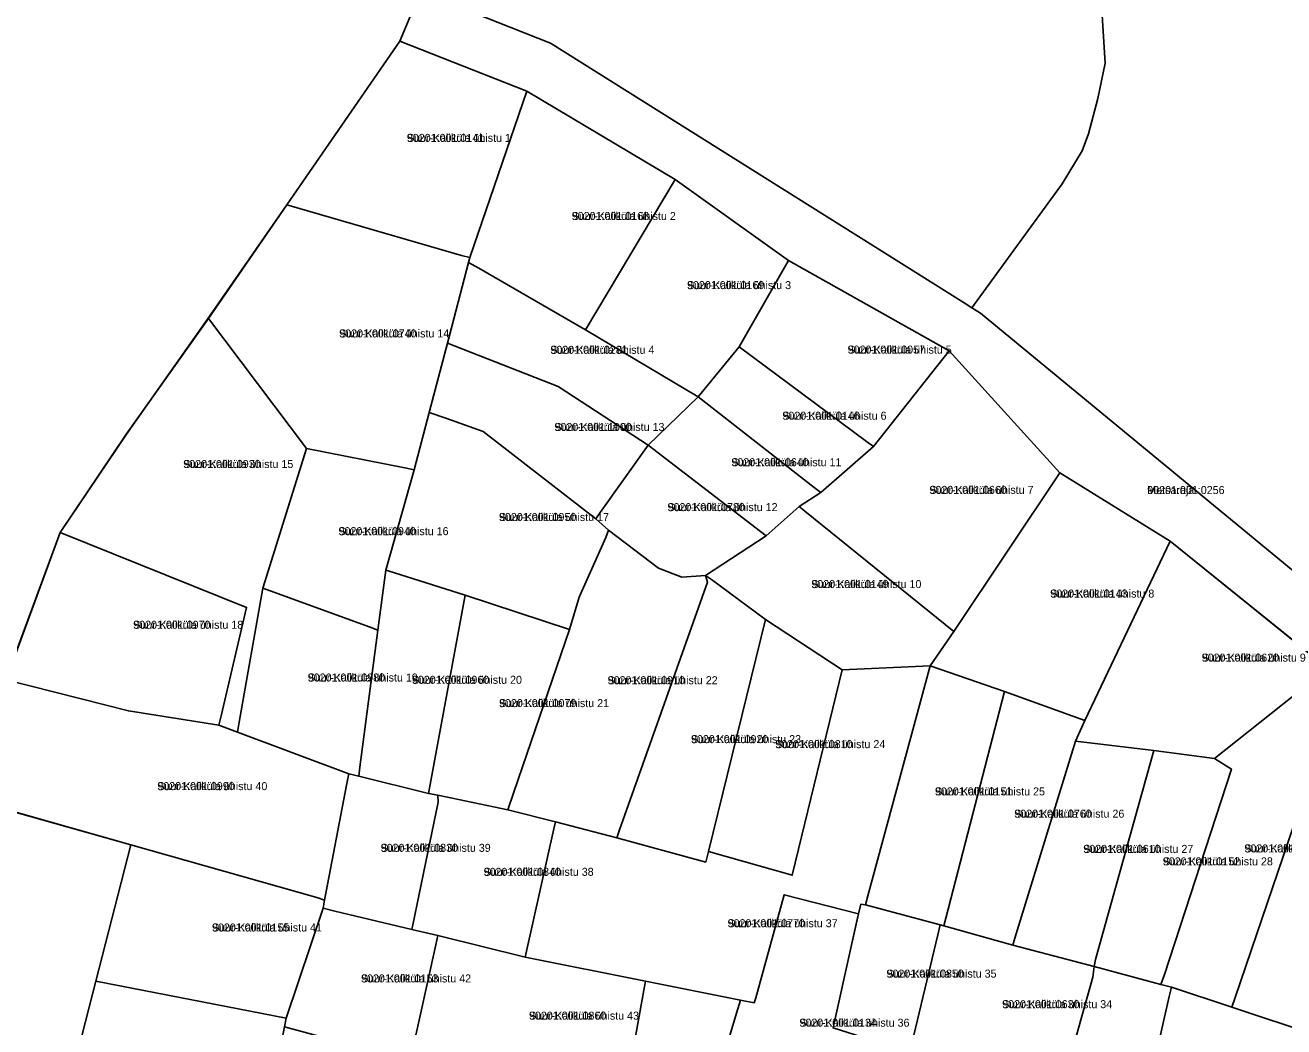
# Model space of a CAD drawing. Extents: x 634518 to 667988, y 6584667 to 6604739.
# Drawn here: x 639044.6 to 639280.5, y 6598932.5 to 6599120.4 of the extents above; entities that cross this region are included whole.
import ezdxf

# ---------------------------------------------------------------- set-up
doc = ezdxf.new("R2010")
doc.units = 0
for name, color, linetype in [('L_AADRESS', 7, 'Continuous'), ('PIIR', 7, 'Continuous'), ('TUNNUS', 7, 'Continuous')]:
    doc.layers.add(name, color=color, linetype=linetype)

msp = doc.modelspace()

# ---------------------------------------------------------------- linework, layer by layer
at = {"layer": 'PIIR'}
for points in [[(638939.52, 6598922.84), (638956.22, 6599045.86), (638963.81, 6599131.43), (639036.47, 6599305.14), (639066.16, 6599272.46), (639113.06, 6599217.03), (639136.09, 6599200.35), (639153.39, 6599188.58), (639173.59, 6599187.14), (639118.65, 6599126.67), (639114.82, 6599117.34), (639093.64, 6599086.65), (639078.76, 6599065.25), (639063.55, 6599043.7), (639051.11, 6599025.24), (639040.95, 6598997.58), (639033.5, 6598975.34), (639064.36, 6598966.67), (639057.8, 6598941.11), (639047.63, 6598901.35)], [(639143.03, 6599116.99), (639118.65, 6599126.67), (639173.59, 6599187.14), (639209.09, 6599197.48), (639243.23, 6599188.58), (639245.19, 6599188.04), (639243.83, 6599180.32), (639244.87, 6599174.9), (639249.45, 6599160.16), (639248.51, 6599133.96), (639246.5, 6599122.2), (639247.04, 6599113.24), (639245.63, 6599106.61), (639243.91, 6599100), (639242.74, 6599096.83), (639238.97, 6599090.63), (639222.06, 6599067.35), (639220.59, 6599068.27)], [(639295.43, 6599007.23), (639223.67, 6599066.34), (639222.06, 6599067.35), (639238.97, 6599090.63), (639242.74, 6599096.83), (639243.91, 6599100), (639245.63, 6599106.61), (639247.04, 6599113.24), (639246.5, 6599122.2), (639248.51, 6599133.96), (639249.45, 6599160.16), (639244.87, 6599174.9), (639243.83, 6599180.32), (639245.19, 6599188.04), (639246.74, 6599187.59), (639297.96, 6599174.25), (639333.44, 6599165.02), (639341.87, 6599103.62), (639355.62, 6599071.96)], [(639166.41, 6599091.4), (639138.6, 6599108), (639114.82, 6599117.34), (639118.65, 6599126.67), (639143.03, 6599116.99), (639220.59, 6599068.27), (639222.06, 6599067.35), (639223.67, 6599066.34), (639295.43, 6599007.23), (639321.52, 6598983.41), (639346.67, 6598960.5), (639375.78, 6598947.36), (639371.97, 6598938.2), (639341.23, 6598951.98), (639313.88, 6598975.86), (639288.82, 6598999.72), (639259.24, 6599023.6), (639238.53, 6599036.45), (639217.78, 6599059.27), (639187.67, 6599076.21)], [(639114.82, 6599117.34), (639138.6, 6599108), (639127.92, 6599076.79), (639126.34, 6599077.18), (639093.64, 6599086.65)], [(639138.6, 6599108), (639166.41, 6599091.4), (639149.6, 6599063.22), (639129.64, 6599074.77), (639127.66, 6599075.84), (639127.92, 6599076.79)], [(639166.41, 6599091.4), (639187.67, 6599076.21), (639178.44, 6599060.02), (639170.71, 6599050.7), (639149.6, 6599063.22)], [(639093.64, 6599086.65), (639126.34, 6599077.18), (639127.92, 6599076.79), (639127.66, 6599075.84), (639123.75, 6599060.75), (639120.32, 6599047.73), (639117.49, 6599036.98), (639115.76, 6599037.37), (639097.31, 6599041.01), (639078.95, 6599065.39)], [(639187.67, 6599076.21), (639217.78, 6599059.27), (639203.59, 6599041.35), (639202.29, 6599042.31), (639178.44, 6599060.02)], [(639127.66, 6599075.84), (639129.64, 6599074.77), (639149.6, 6599063.22), (639170.71, 6599050.7), (639161.38, 6599041.63), (639144.5, 6599052.61), (639125.16, 6599060.19), (639123.75, 6599060.75)], [(639063.59, 6599043.71), (639078.95, 6599065.39), (639097.31, 6599041.01), (639089.13, 6599014.79), (639084.7, 6598989.68), (639084.37, 6598987.8), (639080.9, 6598989.12), (639081.32, 6598990.84), (639086.07, 6599011.17), (639051.1, 6599025.24)], [(639125.16, 6599060.19), (639144.5, 6599052.61), (639161.38, 6599041.63), (639152.37, 6599028.97), (639151.53, 6599027.78), (639130.44, 6599044.2), (639123.43, 6599046.65), (639120.32, 6599047.73), (639123.75, 6599060.75)], [(639178.44, 6599060.02), (639202.29, 6599042.31), (639203.59, 6599041.35), (639193.71, 6599032.74), (639192.49, 6599033.69), (639170.71, 6599050.7)], [(639189.65, 6599030.12), (639193.71, 6599032.74), (639203.59, 6599041.35), (639217.78, 6599059.27), (639238.53, 6599036.45), (639218.66, 6599006.64), (639190.72, 6599029.21)], [(639170.71, 6599050.7), (639192.49, 6599033.69), (639193.71, 6599032.74), (639189.65, 6599030.12), (639183.51, 6599024.63), (639182.41, 6599025.39), (639161.38, 6599041.63)], [(639113.63, 6599017.73), (639112.19, 6599018.15), (639117.49, 6599036.98), (639120.32, 6599047.73), (639123.43, 6599046.65), (639130.44, 6599044.2), (639151.53, 6599027.78), (639153.95, 6599025.65), (639153.43, 6599024.27), (639148.4, 6599013.09), (639146.62, 6599007.02), (639127.04, 6599013.51)], [(639097.31, 6599041.01), (639115.76, 6599037.37), (639117.49, 6599036.98), (639112.19, 6599018.15), (639110.71, 6599006.94), (639109.27, 6599007.46), (639089.13, 6599014.79)], [(639153.95, 6599025.65), (639151.53, 6599027.78), (639152.37, 6599028.97), (639161.38, 6599041.63), (639182.41, 6599025.39), (639183.51, 6599024.63), (639172.13, 6599017.19), (639167.66, 6599016.86), (639163.3, 6599018.57)], [(639238.53, 6599036.45), (639259.24, 6599023.6), (639243.2, 6598989.99), (639228.14, 6598995.39), (639214.22, 6599000.25), (639218.66, 6599006.64)], [(639189.65, 6599030.12), (639190.72, 6599029.21), (639218.66, 6599006.64), (639214.22, 6599000.25), (639197.72, 6598999.5), (639183.33, 6599008.93), (639173.22, 6599016.39), (639172.13, 6599017.19), (639183.51, 6599024.63)], [(639040.98, 6598997.58), (639051.1, 6599025.24), (639086.07, 6599011.17), (639081.32, 6598990.84), (639080.9, 6598989.12), (639063.91, 6598991.76)], [(639135.06, 6598973.24), (639136.18, 6598976.53), (639146.62, 6599007.02), (639148.4, 6599013.09), (639153.43, 6599024.27), (639153.95, 6599025.65), (639163.3, 6599018.57), (639167.66, 6599016.86), (639172.13, 6599017.19), (639172.46, 6599015.92), (639156, 6598969.49), (639155.46, 6598967.96), (639143.98, 6598970.96)], [(639241.46, 6598986.1), (639243.2, 6598989.99), (639259.24, 6599023.6), (639288.8, 6598999.71), (639267.55, 6598982.88), (639256.15, 6598984.38)], [(639107.33, 6598981.23), (639110.71, 6599006.94), (639112.19, 6599018.15), (639113.63, 6599017.73), (639127.04, 6599013.51), (639120.61, 6598978.66), (639120.18, 6598976.31), (639107.11, 6598979.51)], [(639156, 6598969.49), (639172.46, 6599015.92), (639172.13, 6599017.19), (639173.22, 6599016.39), (639183.33, 6599008.93), (639172.64, 6598965.39), (639172.16, 6598963.43), (639155.46, 6598967.96)], [(639084.7, 6598989.68), (639089.13, 6599014.79), (639109.27, 6599007.46), (639110.71, 6599006.94), (639107.33, 6598981.23), (639107.11, 6598979.51), (639105.23, 6598979.95), (639084.37, 6598987.8)], [(639127.04, 6599013.51), (639146.62, 6599007.02), (639136.18, 6598976.53), (639135.06, 6598973.24), (639121.92, 6598975.95), (639120.18, 6598976.31), (639120.61, 6598978.66)], [(639183.33, 6599008.93), (639197.72, 6598999.5), (639188.38, 6598960.95), (639172.64, 6598965.39)], [(639214.22, 6599000.25), (639202.54, 6598957.07), (639202.11, 6598955.44), (639201.23, 6598955.56), (639200.79, 6598953.74), (639186.87, 6598957.3), (639181.54, 6598937.98), (639181.22, 6598937.04), (639178.65, 6598937.56), (639160.85, 6598941.12), (639138.28, 6598945.61), (639138.52, 6598946.71), (639143.68, 6598969.64), (639143.98, 6598970.96), (639155.46, 6598967.96), (639172.16, 6598963.43), (639172.64, 6598965.39), (639188.38, 6598960.95), (639197.72, 6598999.5)], [(639214.22, 6599000.25), (639228.14, 6598995.39), (639217.17, 6598952.94), (639216.79, 6598951.47), (639216.08, 6598951.66), (639202.11, 6598955.44), (639202.54, 6598957.07)], [(639270.78, 6598936.2), (639259.44, 6598939.94), (639257.47, 6598940.45), (639258.17, 6598942.36), (639270.69, 6598980.86), (639267.55, 6598982.88), (639288.8, 6598999.71), (639284.4, 6598976.23), (639271.38, 6598938.02)], [(639270.78, 6598936.2), (639271.38, 6598938.02), (639284.4, 6598976.23), (639288.8, 6598999.71), (639313.89, 6598975.84), (639296.8, 6598926.09), (639286.75, 6598930.92)], [(639040.98, 6598997.58), (639063.91, 6598991.76), (639080.9, 6598989.12), (639084.37, 6598987.8), (639105.23, 6598979.95), (639104.9, 6598978.18), (639100.71, 6598956.26), (639099.22, 6598956.8), (639064.36, 6598966.67), (639033.51, 6598975.39)], [(639216.79, 6598951.47), (639217.17, 6598952.94), (639228.14, 6598995.39), (639243.2, 6598989.99), (639241.46, 6598986.1), (639230.12, 6598949.17), (639229.71, 6598947.85)], [(639256.15, 6598984.38), (639245.2, 6598945.17), (639244.99, 6598943.84), (639229.71, 6598947.85), (639230.12, 6598949.17), (639241.46, 6598986.1)], [(639256.15, 6598984.38), (639267.55, 6598982.88), (639270.69, 6598980.86), (639258.17, 6598942.36), (639257.47, 6598940.45), (639244.99, 6598943.84), (639245.2, 6598945.17)], [(639100.43, 6598954.77), (639100.71, 6598956.26), (639104.9, 6598978.18), (639105.23, 6598979.95), (639107.11, 6598979.51), (639120.18, 6598976.31), (639121.92, 6598975.95), (639122, 6598974.66), (639117.25, 6598951.68), (639117.04, 6598950.79), (639102.61, 6598954.25)], [(639117.04, 6598950.79), (639117.25, 6598951.68), (639122, 6598974.66), (639121.92, 6598975.95), (639135.06, 6598973.24), (639143.98, 6598970.96), (639143.68, 6598969.64), (639138.52, 6598946.71), (639138.28, 6598945.61), (639121.91, 6598949.63)], [(639064.36, 6598966.67), (639099.22, 6598956.8), (639100.71, 6598956.26), (639100.43, 6598954.77), (639093.52, 6598934.15), (639057.8, 6598941.11)], [(639186.87, 6598957.3), (639200.79, 6598953.74), (639200.67, 6598953.2), (639199.3, 6598947.05), (639196.2, 6598933.19), (639196.01, 6598932.34), (639207.23, 6598928.76), (639206.63, 6598926.69), (639200.95, 6598906.88), (639200.52, 6598905.37), (639172.35, 6598913.64), (639172.21, 6598916.11), (639177.91, 6598935.09), (639178.65, 6598937.56), (639181.22, 6598937.04), (639181.54, 6598937.98)], [(639100.43, 6598954.77), (639102.61, 6598954.25), (639117.04, 6598950.79), (639121.91, 6598949.63), (639121.56, 6598947.93), (639117.01, 6598927.26), (639116.7, 6598926.17), (639093.18, 6598932.53), (639093.52, 6598934.15)], [(639196.2, 6598933.19), (639199.3, 6598947.05), (639200.79, 6598953.74), (639201.23, 6598955.56), (639202.11, 6598955.44), (639216.08, 6598951.66), (639215.67, 6598949.8), (639210.76, 6598929.39), (639210.33, 6598927.78), (639207.23, 6598928.76), (639196.01, 6598932.34)], [(639210.33, 6598927.78), (639210.76, 6598929.39), (639215.67, 6598949.8), (639216.08, 6598951.66), (639216.79, 6598951.47), (639229.71, 6598947.85), (639244.99, 6598943.84), (639244.7, 6598941.84), (639239.04, 6598921.58), (639238.71, 6598920.4), (639221.4, 6598924.82)], [(639117.01, 6598927.26), (639121.56, 6598947.93), (639121.91, 6598949.63), (639138.28, 6598945.61), (639160.85, 6598941.12), (639160.67, 6598940.12), (639156.96, 6598919.57), (639156.68, 6598918.13), (639146.93, 6598920.16), (639127.44, 6598924.03), (639116.7, 6598926.17)], [(639239.04, 6598921.58), (639244.7, 6598941.84), (639244.99, 6598943.84), (639257.47, 6598940.45), (639259.44, 6598939.94), (639259.01, 6598938.25), (639254.49, 6598918.07), (639254.25, 6598916.93), (639250.61, 6598917.53), (639238.71, 6598920.4)], [(638939.52, 6598922.84), (639047.63, 6598901.35), (639057.8, 6598941.11), (639093.52, 6598934.15), (639093.18, 6598932.53), (639085.55, 6598894.14), (639061.6, 6598898.73), (639053.29, 6598849.93), (638932.7, 6598820.51)], [(639160.85, 6598941.12), (639178.65, 6598937.56), (639177.91, 6598935.09), (639172.21, 6598916.11), (639172.35, 6598913.64), (639172.49, 6598911.07), (639165.79, 6598879.46), (639165.59, 6598878.52), (639161.31, 6598879.37), (639151.84, 6598881.28), (639141.76, 6598883.34), (639140.02, 6598883.69), (639140.27, 6598885), (639146.63, 6598918.6), (639146.93, 6598920.16), (639156.68, 6598918.13), (639156.96, 6598919.57), (639160.67, 6598940.12)], [(639259.01, 6598938.25), (639259.44, 6598939.94), (639270.78, 6598936.2), (639286.75, 6598930.92), (639285.94, 6598928.24), (639279.92, 6598910.88), (639254.25, 6598916.93), (639254.49, 6598918.07)]]:
    msp.add_lwpolyline(points, close=True, dxfattribs=at)

# ---------------------------------------------------------------- texts
at = {"layer": 'L_AADRESS'}
for s, p in [('Suur-Kaliküla ühistu 1', (639116.12, 6599098.48)), ('Suur-Kaliküla ühistu 2', (639147.03, 6599083.83)), ('Suur-Kaliküla ühistu 3', (639168.64, 6599070.87)), ('Suur-Kaliküla ühistu 14', (639103.44, 6599061.81)), ('Suur-Kaliküla ühistu 4', (639143.02, 6599058.74)), ('Suur-Kaliküla ühistu 5', (639198.75, 6599058.78)), ('Suur-Kaliküla ühistu 6', (639186.53, 6599046.38)), ('Suur-Kaliküla ühistu 13', (639143.79, 6599044.27)), ('Suur-Kaliküla ühistu 15', (639074.21, 6599037.32)), ('Suur-Kaliküla ühistu 11', (639176.96, 6599037.66)), ('Suur-Kaliküla ühistu 7', (639214.09, 6599032.47)), ('Metsaraja', (639254.92, 6599032.44)), ('Suur-Kaliküla ühistu 17', (639133.39, 6599027.38)), ('Suur-Kaliküla ühistu 12', (639164.99, 6599029.24)), ('Suur-Kaliküla ühistu 16', (639103.31, 6599024.73)), ('Suur-Kaliküla ühistu 10', (639191.95, 6599014.81)), ('Suur-Kaliküla ühistu 8', (639236.73, 6599013.03)), ('Suur-Kaliküla ühistu 18', (639064.82, 6599007.18)), ('Suur-Kaliküla ühistu 9', (639265.13, 6599001.02)), ('Suur-Kaliküla ühistu 19', (639097.54, 6598997.29)), ('Suur-Kaliküla ühistu 20', (639117.07, 6598996.86)), ('Suur-Kaliküla ühistu 22', (639153.76, 6598996.78)), ('Suur-Kaliküla ühistu 21', (639133.4, 6598992.49)), ('Suur-Kaliküla ühistu 23', (639169.39, 6598985.73)), ('Suur-Kaliküla ühistu 24', (639185.18, 6598984.79)), ('Suur-Kaliküla ühistu 40', (639069.34, 6598976.92)), ('Suur-Kaliküla ühistu 25', (639215.12, 6598975.93)), ('Suur-Kaliküla ühistu 26', (639230, 6598971.75)), ('Suur-Kaliküla ühistu 39', (639111.21, 6598965.35)), ('Suur-Kaliküla ühistu 27', (639242.93, 6598965.15)), ('Suur-Kaliküla ühistu 29', (639273.13, 6598965.24)), ('Suur-Kaliküla ühistu 28', (639257.84, 6598962.81)), ('Suur-Kaliküla ühistu 38', (639130.51, 6598960.85)), ('Suur-Kaliküla ühistu 41', (639079.58, 6598950.41)), ('Suur-Kaliküla ühistu 37', (639176.25, 6598951.21)), ('Suur-Kaliküla ühistu 42', (639107.54, 6598940.86)), ('Suur-Kaliküla ühistu 35', (639206.04, 6598941.76)), ('Suur-Kaliküla ühistu 34', (639227.72, 6598936.03)), ('Suur-Kaliküla ühistu 43', (639139.01, 6598933.88)), ('Suur-Kaliküla ühistu 36', (639189.72, 6598932.56))]:
    msp.add_text(s, height=1.5, dxfattribs=at).set_placement(p)
at = {"layer": 'TUNNUS'}
for s, p in [('90201:001:0141', (639116.12, 6599098.48)), ('90201:001:0168', (639147.03, 6599083.83)), ('90201:001:0169', (639168.64, 6599070.87)), ('90201:001:0740', (639103.44, 6599061.81)), ('90201:001:0281', (639143.02, 6599058.74)), ('90201:001:0057', (639198.75, 6599058.78)), ('90201:001:0146', (639186.53, 6599046.38)), ('90201:001:1000', (639143.79, 6599044.27)), ('90201:001:0930', (639074.21, 6599037.32)), ('90201:001:0640', (639176.96, 6599037.66)), ('90201:001:0660', (639214.09, 6599032.47)), ('90201:001:0256', (639254.92, 6599032.44)), ('90201:001:0950', (639133.39, 6599027.38)), ('90201:001:0780', (639164.99, 6599029.24)), ('90201:001:0940', (639103.31, 6599024.73)), ('90201:001:0149', (639191.95, 6599014.81)), ('90201:001:0143', (639236.73, 6599013.03)), ('90201:001:0970', (639064.82, 6599007.18)), ('90201:001:0620', (639265.13, 6599001.02)), ('90201:001:0980', (639097.54, 6598997.29)), ('90201:001:0960', (639117.07, 6598996.86)), ('90201:001:0910', (639153.76, 6598996.78)), ('90201:001:0079', (639133.4, 6598992.49)), ('90201:001:0920', (639169.39, 6598985.73)), ('90201:001:0810', (639185.18, 6598984.79)), ('90201:001:0990', (639069.34, 6598976.92)), ('90201:001:0151', (639215.12, 6598975.93)), ('90201:001:0760', (639230, 6598971.75)), ('90201:001:0830', (639111.21, 6598965.35)), ('90201:001:0610', (639242.93, 6598965.15)), ('90201:001:0710', (639273.13, 6598965.24)), ('90201:001:0152', (639257.84, 6598962.81)), ('90201:001:0840', (639130.51, 6598960.85)), ('90201:001:0155', (639079.58, 6598950.41)), ('90201:001:0770', (639176.25, 6598951.21)), ('90201:001:0153', (639107.54, 6598940.86)), ('90201:001:0850', (639206.04, 6598941.76)), ('90201:001:0630', (639227.72, 6598936.03)), ('90201:001:0860', (639139.01, 6598933.88)), ('90201:001:0134', (639189.72, 6598932.56))]:
    msp.add_text(s, height=1.5, dxfattribs=at).set_placement(p)

doc.saveas('drawing.dxf')
